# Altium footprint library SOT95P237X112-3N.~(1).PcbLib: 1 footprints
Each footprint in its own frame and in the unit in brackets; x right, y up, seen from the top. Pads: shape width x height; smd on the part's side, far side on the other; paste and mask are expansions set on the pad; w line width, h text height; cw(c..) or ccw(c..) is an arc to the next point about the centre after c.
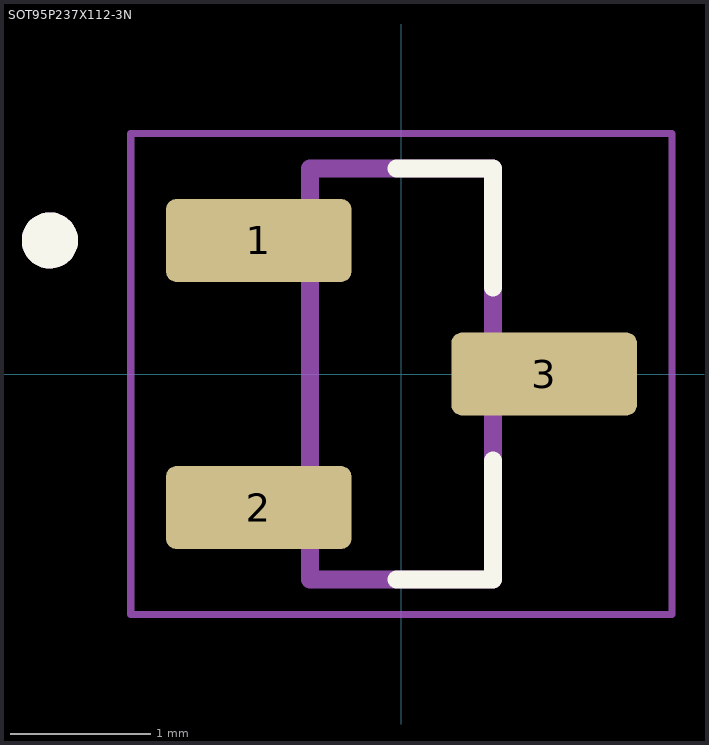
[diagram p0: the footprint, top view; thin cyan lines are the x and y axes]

## SOT95P237X112-3N [mm]
height 1.12
pads (3):
  rrect25% 1.32x0.59 smd: 1(-1.015,0.95) 2(-1.015,-0.95) 3(1.015,0)
Top Overlay:
  circle w0.2: c-2.5,0.95 r0.1
  lines w0.127: -0.035,-1.46 0.65,-1.46 0.65,-0.615 ; -0.035,1.46 0.65,1.46 0.65,0.615
Mechanical 13:
  circle w0.2: c-2.5,0.95 r0.1
  lines w0.127: -0.65,-1.46 -0.65,1.46 0.65,1.46 0.65,-1.46 -0.65,-1.46
Mechanical 15:
  lines w0.05: -1.925,-1.71 -1.925,1.71 1.925,1.71 1.925,-1.71 -1.925,-1.71
3D body "step_temp.STEP": height 1.12, standoff 0, extent -1.188,-1.46 1.188,1.46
